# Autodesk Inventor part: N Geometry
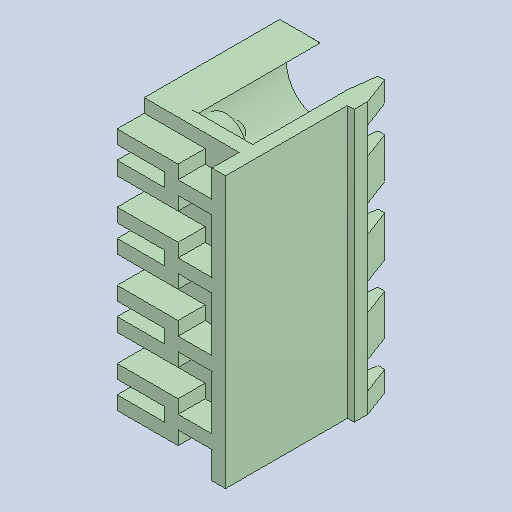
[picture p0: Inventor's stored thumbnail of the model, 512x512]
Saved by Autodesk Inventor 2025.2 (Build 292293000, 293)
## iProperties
Created: 2025-04
Part Number: N Geometry
Material: Generic
Description: PART-N Geometry-DESC
Document SubType Name: Modeling
Designer: BennF
Density: 1 g/cm^3
Appearance: Default
Author: BennF
Revision Number: NONE
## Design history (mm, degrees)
feature "Solid"
body "Solid1"
